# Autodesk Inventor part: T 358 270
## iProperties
Created: 2005-10
Part Number: T 358 270
Material: 1.0718.07
Document SubType Name: Modeling
Designer: I.Baliuc
Manufacturer: Standard
Standards Organization: Custom
Description: Schaltscheibe, rechts
Density: 7.84 g/cm^3
Mass: 414.037 g
Surface Area: 136.045 cm^2
Volume: 52.8108 cm^3
Title: Schaltscheibe, rechts
Company: Mayer & Müller AG Schaltgeräte
Abmessung: Rd 80
HalbzeugNorm: DIN 671
Zweck: Trenner HSE/HSD
Author: T.Messerschmitt
Comments: Trenner HSE / HSD
Revision Number: 358270
Keywords: 380098
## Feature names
1. Drehung1 [Revolution]
2. Extrusion2
3. Bohrung_M12 [Hole]
4. Bohrung_M8 [Hole]
5. Ankörnung [Hole]
